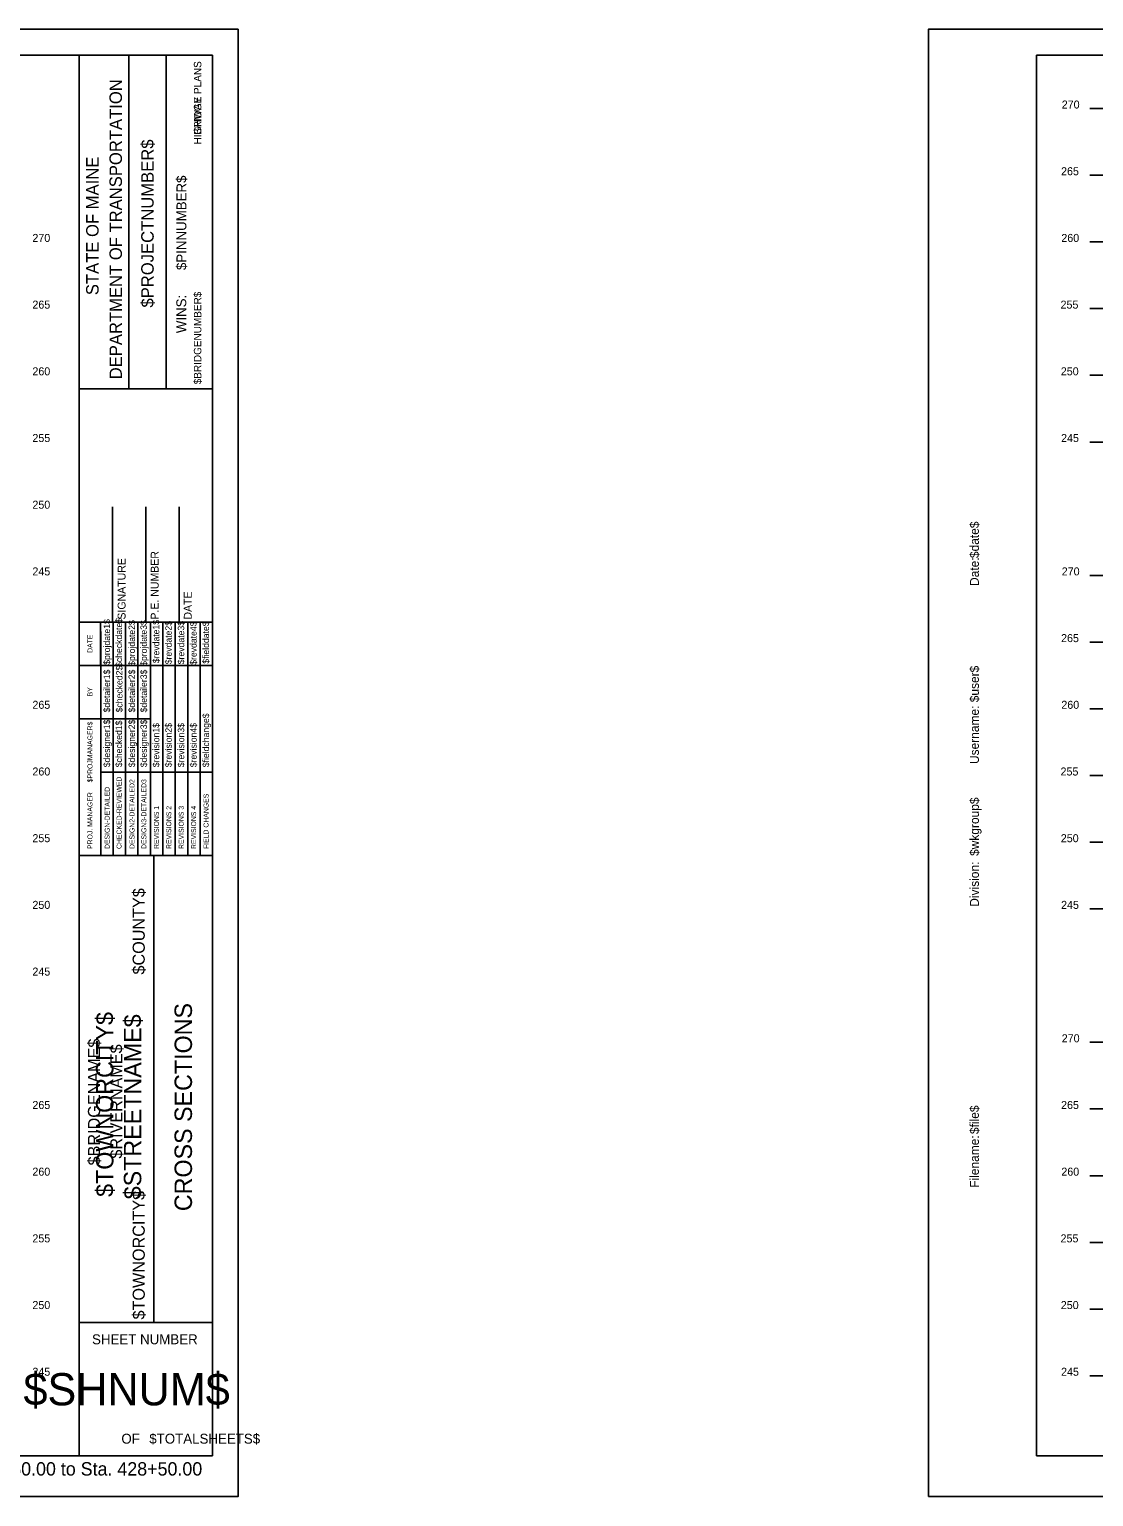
# Model space of a CAD drawing. Extents: x 1168600 to 1177589, y 610178 to 611246.
# Drawn here: x 1175478.4 to 1175558.2, y 610900.5 to 611010.5 of the extents above; entities that cross this region are included whole.
import ezdxf

# ---------------------------------------------------------------- set-up
doc = ezdxf.new("R2010")
doc.units = 0
for name, color, linetype in [('_Construction', 7, 'Continuous'), ('BORDER', 7, 'Continuous'), ('H_V ANNOTATION', 7, 'Continuous'), ('MAJOR', 7, 'Continuous')]:
    doc.layers.add(name, color=color, linetype=linetype)

msp = doc.modelspace()

# ---------------------------------------------------------------- linework, layer by layer
at = {"layer": '_Construction'}
for p, q in [((1175492.15, 611008.6), (1175332.15, 611008.6)), ((1175482.15, 610903.6), (1175482.15, 611008.6)), ((1175485.88, 610983.59), (1175485.88, 611008.59)), ((1175488.67, 610983.59), (1175488.67, 611008.59)), ((1175492.15, 610903.6), (1175492.15, 611008.6)), ((1175713.91, 611008.6), (1175553.91, 611008.6)), ((1175553.91, 611008.6), (1175553.91, 610903.6)), ((1175482.15, 610983.59), (1175492.15, 610983.59)), ((1175484.65, 610966.1), (1175484.65, 610974.75)), ((1175487.15, 610966.1), (1175487.15, 610974.75)), ((1175489.65, 610966.1), (1175489.65, 610974.75)), ((1175482.15, 610966.1), (1175492.15, 610966.1)), ((1175482.15, 610948.6), (1175492.15, 610948.6)), ((1175487.74, 610913.6), (1175487.74, 610948.6)), ((1175482.15, 610913.6), (1175492.15, 610913.6)), ((1175332.15, 610903.6), (1175492.15, 610903.6)), ((1175553.91, 610903.6), (1175713.91, 610903.6))]:
    msp.add_line(p, q, dxfattribs=at)
for points in [[(1175324.06, 610900.54), (1175494.06, 610900.54), (1175494.06, 611010.54), (1175324.06, 611010.54)], [(1175545.81, 610900.54), (1175715.81, 610900.54), (1175715.81, 611010.54), (1175545.81, 611010.54)]]:
    msp.add_lwpolyline(points, close=True, dxfattribs=at)
for points in [[(1175483.76, 610962.85), (1175483.76, 610966.1)], [(1175483.77, 610948.6), (1175483.77, 610965.39)], [(1175484.7, 610948.6), (1175484.7, 610966.1)], [(1175485.63, 610966.1), (1175485.63, 610948.6)], [(1175486.56, 610948.6), (1175486.56, 610966.1)], [(1175487.49, 610948.6), (1175487.49, 610966.1)], [(1175488.42, 610948.6), (1175488.42, 610966.1)], [(1175489.36, 610948.6), (1175489.36, 610966.1)], [(1175490.29, 610948.6), (1175490.29, 610966.1)], [(1175491.22, 610948.6), (1175491.22, 610966.1)], [(1175482.15, 610962.85), (1175492.15, 610962.85)], [(1175482.15, 610958.85), (1175483.77, 610958.85)], [(1175483.76, 610958.85), (1175487.49, 610958.85)], [(1175483.76, 610954.85), (1175492.15, 610954.85)]]:
    msp.add_lwpolyline(points, dxfattribs=at)
at = {"layer": 'MAJOR'}
for p, q in [((1175557.9, 611004.6), (1175558.91, 611004.6)), ((1175557.9, 610999.6), (1175558.91, 610999.6)), ((1175557.9, 610994.6), (1175558.91, 610994.6)), ((1175557.9, 610989.6), (1175558.91, 610989.6)), ((1175557.9, 610984.6), (1175558.91, 610984.6)), ((1175557.9, 610979.6), (1175558.91, 610979.6)), ((1175557.9, 610969.6), (1175558.91, 610969.6)), ((1175557.9, 610964.6), (1175558.91, 610964.6)), ((1175557.9, 610959.6), (1175558.91, 610959.6)), ((1175557.9, 610954.6), (1175558.91, 610954.6)), ((1175557.9, 610949.6), (1175558.91, 610949.6)), ((1175557.9, 610944.6), (1175558.91, 610944.6)), ((1175557.9, 610934.6), (1175558.91, 610934.6)), ((1175557.9, 610929.6), (1175558.91, 610929.6)), ((1175557.9, 610924.6), (1175558.91, 610924.6)), ((1175557.9, 610919.6), (1175558.91, 610919.6)), ((1175557.9, 610914.6), (1175558.91, 610914.6)), ((1175557.9, 610909.6), (1175558.91, 610909.6))]:
    msp.add_line(p, q, dxfattribs=at)

# ---------------------------------------------------------------- texts
at = {"layer": '_Construction'}
for s, height, rotation, p in [('HIGHWAY PLANS', 0.559, 90, (1175491.31, 611001.91)), ('BRIDGE PLANS', 0.559, 90, (1175491.31, 611002.62)), ('DEPARTMENT OF TRANSPORTATION', 0.9318, 90, (1175485.36, 610984.3)), ('$PROJECTNUMBER$', 0.9318, 90, (1175487.74, 610989.68)), ('STATE OF MAINE', 0.9318, 90, (1175483.61, 610990.61)), ('$PINNUMBER$', 0.7453, 90, (1175490.19, 610992.49)), ('$BRIDGENUMBER$', 0.559, 90, (1175491.31, 610983.93)), ('$date$', 0.67, 90, (1175549.59, 610970.9)), ('SIGNATURE', 0.591, 90, (1175485.63, 610966.29)), ('P.E. NUMBER', 0.5906, 90, (1175488.11, 610966.29)), ('Date:', 0.67, 90, (1175549.59, 610968.81)), ('DATE', 0.591, 90, (1175490.59, 610966.29)), ('$checkdate$', 0.4845, 90, (1175485.37, 610962.74)), ('$projdate1$', 0.4845, 90, (1175484.47, 610962.9)), ('$projdate2$', 0.4845, 90, (1175486.34, 610962.82)), ('$projdate3$', 0.4845, 90, (1175487.23, 610962.82)), ('$revdate1$', 0.485, 90, (1175488.16, 610963.02)), ('$revdate2$', 0.485, 90, (1175489.09, 610962.94)), ('$revdate3$', 0.485, 90, (1175490.03, 610962.94)), ('$revdate4$', 0.485, 90, (1175490.96, 610962.9)), ('$fielddate$', 0.4845, 90, (1175491.89, 610962.98)), ('DATE', 0.371, 90, (1175483.15, 610963.8)), ('$detailer1$', 0.4845, 90, (1175484.47, 610959.33)), ('$checked2$', 0.485, 90, (1175485.4, 610959.33)), ('$detailer2$', 0.4845, 90, (1175486.34, 610959.33)), ('$detailer3$', 0.4845, 90, (1175487.23, 610959.33)), ('$user$', 0.67, 90, (1175549.59, 610960.09)), ('BY', 0.371, 90, (1175483.15, 610960.53)), ('$designer1$', 0.4845, 90, (1175484.47, 610955.22)), ('$checked1$', 0.485, 90, (1175485.37, 610955.22)), ('$designer2$', 0.4845, 90, (1175486.34, 610955.22)), ('$designer3$', 0.4845, 90, (1175487.23, 610955.22)), ('$fieldchange$', 0.4845, 90, (1175491.89, 610955.22)), ('Username:', 0.67, 90, (1175549.59, 610955.46)), ('$PROJMANAGER$', 0.3727, 90, (1175483.15, 610954.09)), ('$revision1$', 0.4845, 90, (1175488.16, 610955.22)), ('$revision2$', 0.4845, 90, (1175489.09, 610955.22)), ('$revision3$', 0.4845, 90, (1175490.03, 610955.22)), ('$revision4$', 0.4845, 90, (1175490.96, 610955.22)), ('CHECKED-REVIEWED', 0.3727, 90, (1175485.33, 610949.09)), ('DESIGN-DETAILED', 0.3727, 90, (1175484.44, 610949.09)), ('DESIGN2-DETAILED2', 0.3727, 90, (1175486.3, 610949.09)), ('DESIGN3-DETAILED3', 0.3727, 90, (1175487.19, 610949.09)), ('PROJ. MANAGER', 0.3727, 90, (1175483.15, 610949.09)), ('REVISIONS 1', 0.3727, 90, (1175488.13, 610949.09)), ('REVISIONS 2', 0.3727, 90, (1175489.06, 610949.09)), ('REVISIONS 3', 0.3727, 90, (1175489.99, 610949.09)), ('REVISIONS 4', 0.3727, 90, (1175490.92, 610949.09)), ('FIELD CHANGES', 0.3727, 90, (1175491.85, 610949.09)), ('$wkgroup$', 0.67, 90, (1175549.59, 610948.57)), ('Division:', 0.67, 90, (1175549.59, 610944.76)), ('$COUNTY$', 0.907, 90, (1175487.07, 610939.68)), ('$TOWNORCITY$', 1.3043, 90, (1175484.72, 610923.01)), ('CROSS SECTIONS', 1.3043, 90, (1175490.61, 610921.94)), ('$STREETNAME$', 1.3043, 90, (1175486.81, 610922.83)), ('$BRIDGENAME$', 0.9072, 90, (1175483.72, 610925.37)), ('$RIVERNAME$', 0.9072, 90, (1175485.39, 610925.88)), ('$file$', 0.67, 90, (1175549.59, 610927.72)), ('Filename:', 0.67, 90, (1175549.59, 610923.69)), ('$TOWNORCITY$', 0.9072, 90, (1175487.07, 610913.82)), ('SHEET NUMBER', 0.7453, 360, (1175483.12, 610911.96)), ('$SHNUM$', 2.419, 360, (1175477.98, 610907.38)), ('OF', 0.745, 360, (1175485.32, 610904.51)), ('$TOTALSHEETS$', 0.7453, 360, (1175487.41, 610904.51))]:
    msp.add_text(s, height=height, rotation=rotation, dxfattribs=at).set_placement(p)
at = {"layer": 'BORDER'}
msp.add_text('WINS:', height=0.745, rotation=90, dxfattribs=at).set_placement((1175490.18, 610987.76))
at = {"layer": 'H_V ANNOTATION'}
for s, height, p in [('270', 0.6, (1175555.8, 611004.6)), ('265', 0.6, (1175555.75, 610999.6)), ('270', 0.6, (1175478.65, 610994.6)), ('260', 0.6, (1175555.77, 610994.6)), ('265', 0.6, (1175478.65, 610989.6)), ('255', 0.6, (1175555.71, 610989.6)), ('260', 0.6, (1175478.65, 610984.6)), ('250', 0.6, (1175555.73, 610984.6)), ('255', 0.6, (1175478.65, 610979.6)), ('245', 0.6, (1175555.75, 610979.6)), ('250', 0.6, (1175478.65, 610974.6)), ('245', 0.6, (1175478.65, 610969.6)), ('270', 0.6, (1175555.8, 610969.6)), ('265', 0.6, (1175555.75, 610964.6)), ('265', 0.6, (1175478.65, 610959.6)), ('260', 0.6, (1175555.77, 610959.6)), ('260', 0.6, (1175478.65, 610954.6)), ('255', 0.6, (1175555.71, 610954.6)), ('255', 0.6, (1175478.65, 610949.6)), ('250', 0.6, (1175555.73, 610949.6)), ('250', 0.6, (1175478.65, 610944.6)), ('245', 0.6, (1175555.75, 610944.6)), ('245', 0.6, (1175478.65, 610939.6)), ('270', 0.6, (1175555.8, 610934.6)), ('265', 0.6, (1175478.65, 610929.6)), ('265', 0.6, (1175555.75, 610929.6)), ('260', 0.6, (1175478.65, 610924.6)), ('260', 0.6, (1175555.77, 610924.6)), ('255', 0.6, (1175478.65, 610919.6)), ('255', 0.6, (1175555.71, 610919.6)), ('250', 0.6, (1175478.65, 610914.6)), ('250', 0.6, (1175555.73, 610914.6)), ('245', 0.6, (1175478.65, 610909.6)), ('245', 0.6, (1175555.75, 610909.6)), ('Sta. 427+50.00 to Sta. 428+50.00', 1.0002, (1175471.3, 610902.12))]:
    msp.add_text(s, height=height, dxfattribs=at).set_placement(p)

doc.saveas('drawing.dxf')
